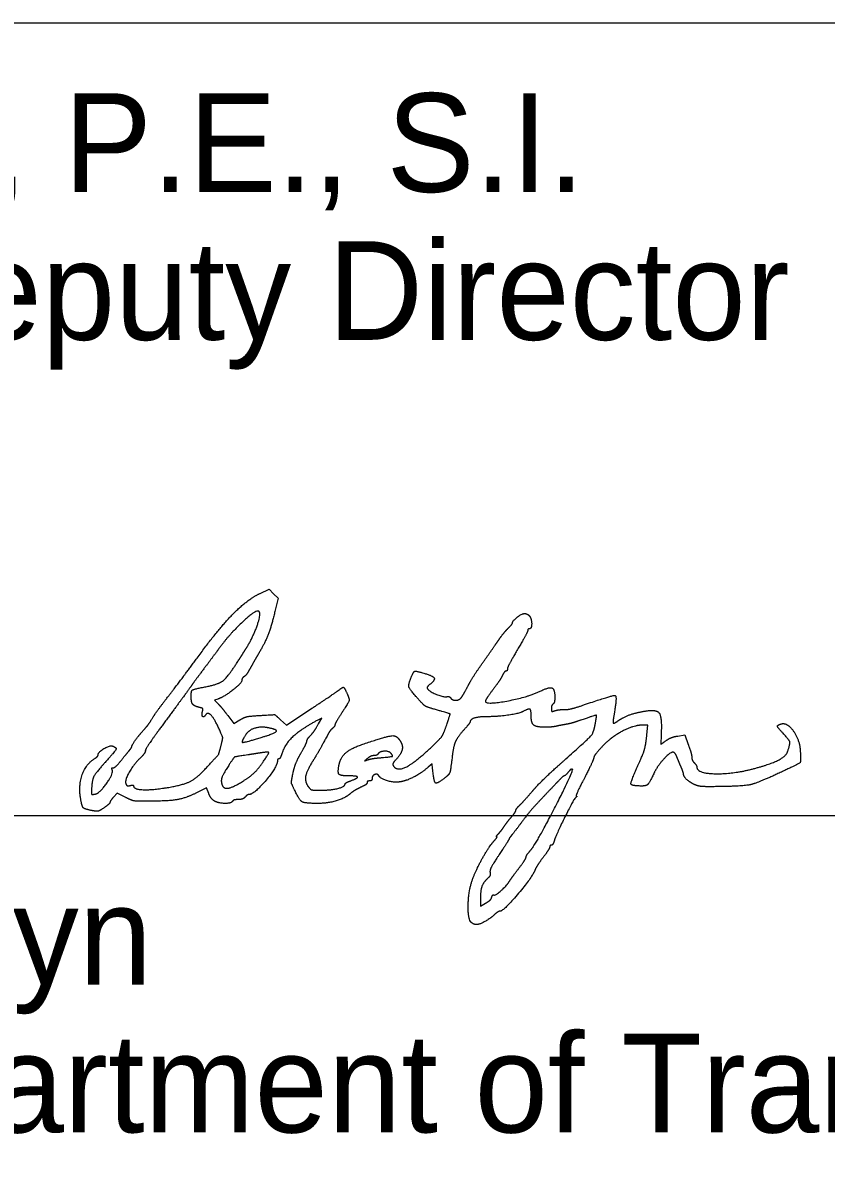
# Model space of a CAD drawing. Extents: x 0 to 34, y 0 to 22.
# Drawn here: x 25.648 to 26.788, y 7.199 to 8.816 of the extents above; entities that cross this region are included whole.
import ezdxf

# ---------------------------------------------------------------- set-up
doc = ezdxf.new("R2010")
doc.units = 0
doc.layers.add('SH_Data', color=7, linetype='Continuous')
doc.layers.add('SH_Text', color=7, linetype='Continuous')

msp = doc.modelspace()

# ---------------------------------------------------------------- linework, layer by layer
at = {"layer": 'SH_Data'}
for p, q in [((24.5, 8.816), (28, 8.816)), ((24.5, 7.691), (28, 7.691))]:
    msp.add_line(p, q, dxfattribs=at)
at = {"layer": 'SH_Text'}
for points in [[(25.9853, 8.0062), (25.9979, 8.012), (26.0042, 8.0057), (26.0106, 7.9993), (26.0062, 7.9806)], [(25.9253, 7.8562), (25.9203, 7.8546), (25.9255, 7.8495)], [(25.9392, 7.8328), (25.9477, 7.8213), (25.9565, 7.8265)], [(26.0143, 7.8265), (26.0224, 7.8189), (26.0587, 7.843)], [(26.0682, 7.8212), (26.0726, 7.8292), (26.0671, 7.8263)], [(26.534, 7.8053), (26.5355, 7.8191), (26.5277, 7.8191)], [(26.5779, 7.8037), (26.5876, 7.8053), (26.5926, 7.7917)], [(26.23, 7.7576), (26.2293, 7.7644), (26.2234, 7.7593)], [(25.7937, 7.7169), (25.7822, 7.7227), (25.7771, 7.7169)], [(25.9123, 7.722), (25.909, 7.73), (25.8951, 7.7231)], [(26.2977, 7.5714), (26.2977, 7.5621), (26.3052, 7.5664)]]:
    msp.add_lwpolyline(points, dxfattribs=at)
for points in [[(25.8957, 7.9143), (25.9254, 7.9549), (25.9672, 7.9978), (25.9853, 8.0062)], [(25.9838, 7.9804), (25.9802, 7.984), (25.9416, 7.9483), (25.9262, 7.927)], [(25.9655, 7.9283), (25.9749, 7.9432), (25.9869, 7.9773), (25.9838, 7.9804)], [(26.0062, 7.9806), (26.0012, 7.9595), (25.992, 7.9359), (25.9826, 7.9199)], [(26.3433, 7.9643), (26.3433, 7.9671), (26.3565, 7.9774), (26.3602, 7.9775)], [(26.3602, 7.9775), (26.3623, 7.9775), (26.3652, 7.9762), (26.3668, 7.9747)], [(26.3668, 7.9747), (26.3703, 7.9712), (26.3707, 7.9559), (26.3673, 7.9559)], [(26.3367, 7.9562), (26.3403, 7.9598), (26.3433, 7.9634), (26.3433, 7.9643)], [(26.3229, 7.9389), (26.3269, 7.9448), (26.3331, 7.9525), (26.3367, 7.9562)], [(26.3649, 7.9534), (26.3649, 7.952), (26.3584, 7.9399), (26.3505, 7.9266)], [(26.3673, 7.9559), (26.366, 7.9559), (26.3649, 7.9548), (26.3649, 7.9534)], [(25.9262, 7.927), (25.9226, 7.9221), (25.9132, 7.9094), (25.9053, 7.8989)], [(25.955, 7.9117), (25.9583, 7.9169), (25.963, 7.9244), (25.9655, 7.9283)], [(26.3013, 7.9079), (26.3092, 7.9192), (26.319, 7.9331), (26.3229, 7.9389)], [(26.3505, 7.9266), (26.3426, 7.9132), (26.3361, 7.9008), (26.3361, 7.8991)], [(25.8555, 7.8609), (25.8644, 7.8722), (25.8825, 7.8963), (25.8957, 7.9143)], [(25.9052, 7.873), (25.9258, 7.8768), (25.9398, 7.8877), (25.955, 7.9117)], [(25.9826, 7.9199), (25.9791, 7.914), (25.9739, 7.9048), (25.971, 7.8995)], [(25.9053, 7.8989), (25.8974, 7.8884), (25.8893, 7.8774), (25.8873, 7.8745)], [(25.971, 7.8995), (25.9682, 7.8943), (25.9644, 7.8891), (25.9626, 7.888)], [(26.1992, 7.8862), (26.203, 7.8952), (26.2061, 7.8963), (26.2188, 7.8925)], [(26.2188, 7.8925), (26.2308, 7.889), (26.2337, 7.8828), (26.226, 7.8769)], [(26.2799, 7.8743), (26.2837, 7.8816), (26.2933, 7.8967), (26.3013, 7.9079)], [(26.3341, 7.8959), (26.333, 7.8959), (26.3306, 7.893), (26.3288, 7.8893)], [(26.3361, 7.8991), (26.3361, 7.8973), (26.3352, 7.8959), (26.3341, 7.8959)], [(25.9593, 7.8826), (25.9593, 7.8788), (25.9335, 7.8588), (25.9253, 7.8562)], [(25.9626, 7.888), (25.9608, 7.887), (25.9593, 7.8845), (25.9593, 7.8826)], [(26.209, 7.8568), (26.1975, 7.8698), (26.1953, 7.8766), (26.1992, 7.8862)], [(26.226, 7.8769), (26.2233, 7.8749), (26.2218, 7.872), (26.2228, 7.8707)], [(26.3288, 7.8893), (26.3271, 7.8857), (26.3209, 7.8766), (26.3152, 7.8691)], [(25.834, 7.8315), (25.837, 7.8363), (25.8467, 7.8495), (25.8555, 7.8609)], [(25.8873, 7.8745), (25.8853, 7.8715), (25.87, 7.8506), (25.8532, 7.8279)], [(25.8873, 7.8609), (25.8873, 7.8677), (25.8914, 7.8705), (25.9052, 7.873)], [(25.8983, 7.8445), (25.8911, 7.8463), (25.8873, 7.852), (25.8873, 7.8609)], [(26.0587, 7.843), (26.0786, 7.8563), (26.0962, 7.8682), (26.0978, 7.8695)], [(26.0978, 7.8695), (26.1023, 7.8733), (26.1047, 7.8724), (26.1077, 7.8658)], [(26.1077, 7.8658), (26.1121, 7.8562), (26.1111, 7.8521), (26.1009, 7.8362)], [(26.2228, 7.8707), (26.2254, 7.8669), (26.2453, 7.8587), (26.25, 7.8595)], [(26.2706, 7.8581), (26.2719, 7.8598), (26.2761, 7.8671), (26.2799, 7.8743)], [(26.3152, 7.8691), (26.3096, 7.8617), (26.3049, 7.8544), (26.3049, 7.8531)], [(26.3049, 7.8531), (26.3049, 7.8478), (26.3645, 7.8587), (26.3825, 7.8673)], [(26.3825, 7.8673), (26.3955, 7.8735), (26.4033, 7.8703), (26.4033, 7.8589)], [(26.4456, 7.8482), (26.486, 7.8621), (26.4919, 7.8605), (26.4878, 7.8366)], [(25.9034, 7.8382), (25.9043, 7.8418), (25.9031, 7.8433), (25.8983, 7.8445)], [(25.9255, 7.8495), (25.9283, 7.8467), (25.9345, 7.8392), (25.9392, 7.8328)], [(26.2325, 7.8416), (26.2217, 7.8447), (26.2168, 7.8479), (26.209, 7.8568)], [(26.25, 7.8595), (26.2522, 7.8599), (26.2548, 7.859), (26.2556, 7.8577)], [(26.2556, 7.8577), (26.2578, 7.8542), (26.2678, 7.8545), (26.2706, 7.8581)], [(26.4009, 7.8491), (26.3996, 7.8483), (26.3985, 7.8455), (26.3985, 7.8428)], [(26.4033, 7.8589), (26.4033, 7.8544), (26.4022, 7.85), (26.4009, 7.8491)], [(26.4168, 7.8412), (26.421, 7.841), (26.4339, 7.8442), (26.4456, 7.8482)], [(25.8177, 7.8096), (25.8243, 7.8169), (25.8285, 7.8227), (25.834, 7.8315)], [(25.8532, 7.8279), (25.8364, 7.8053), (25.8226, 7.7851), (25.8225, 7.7831)], [(25.9077, 7.8335), (25.9052, 7.8296), (25.902, 7.8331), (25.9034, 7.8382)], [(25.9265, 7.8149), (25.9203, 7.8285), (25.9106, 7.8382), (25.9077, 7.8335)], [(25.9565, 7.8265), (25.963, 7.8304), (25.9706, 7.8321), (25.9857, 7.8329)], [(25.9857, 7.8329), (26.006, 7.8341), (26.0062, 7.8341), (26.0143, 7.8265)], [(26.1009, 7.8362), (26.0956, 7.8281), (26.0913, 7.8205), (26.0913, 7.8194)], [(26.2493, 7.8179), (26.255, 7.8347), (26.2546, 7.8353), (26.2325, 7.8416)], [(26.3075, 7.8311), (26.296, 7.8311), (26.2833, 7.8274), (26.2833, 7.824)], [(26.3583, 7.8385), (26.3527, 7.8355), (26.3225, 7.8311), (26.3075, 7.8311)], [(26.3697, 7.8338), (26.3697, 7.8411), (26.366, 7.8427), (26.3583, 7.8385)], [(26.389, 7.8162), (26.3766, 7.8162), (26.3697, 7.8225), (26.3697, 7.8338)], [(26.3985, 7.8428), (26.3985, 7.8389), (26.3995, 7.8383), (26.4039, 7.8397)], [(26.4039, 7.8397), (26.4069, 7.8407), (26.4127, 7.8413), (26.4168, 7.8412)], [(26.4609, 7.8216), (26.463, 7.8331), (26.4613, 7.8335), (26.4403, 7.8262)], [(26.4878, 7.8366), (26.4865, 7.829), (26.4857, 7.8224), (26.4862, 7.8219)], [(26.4938, 7.8257), (26.501, 7.8308), (26.5192, 7.8371), (26.5329, 7.8393)], [(26.5329, 7.8393), (26.5476, 7.8416), (26.5552, 7.8311), (26.5544, 7.8099)], [(25.9298, 7.7903), (25.9323, 7.8002), (25.932, 7.8024), (25.9265, 7.8149)], [(25.9975, 7.8152), (25.9866, 7.8174), (25.9693, 7.8123), (25.9649, 7.8057)], [(25.9869, 7.8017), (26.0061, 7.8076), (26.0101, 7.8127), (25.9975, 7.8152)], [(26.0671, 7.8263), (26.0437, 7.8137), (26.021, 7.793), (26.0168, 7.7806)], [(26.0554, 7.8031), (26.0608, 7.8091), (26.0633, 7.8127), (26.0682, 7.8212)], [(26.0877, 7.8144), (26.0858, 7.8128), (26.0827, 7.8086), (26.0809, 7.8051)], [(26.0913, 7.8194), (26.0913, 7.8182), (26.0897, 7.816), (26.0877, 7.8144)], [(26.231, 7.7906), (26.2414, 7.8006), (26.2455, 7.8068), (26.2493, 7.8179)], [(26.2739, 7.8119), (26.2655, 7.8024), (26.2597, 7.7899), (26.2581, 7.7771)], [(26.2833, 7.824), (26.2833, 7.8231), (26.2791, 7.8177), (26.2739, 7.8119)], [(26.4057, 7.8176), (26.4024, 7.8168), (26.3949, 7.8162), (26.389, 7.8162)], [(26.4189, 7.8202), (26.4149, 7.8195), (26.409, 7.8184), (26.4057, 7.8176)], [(26.4161, 7.7686), (26.4516, 7.8002), (26.4585, 7.8083), (26.4609, 7.8216)], [(26.4403, 7.8262), (26.4325, 7.8235), (26.4229, 7.8208), (26.4189, 7.8202)], [(26.5277, 7.8191), (26.515, 7.8191), (26.4812, 7.8007), (26.4691, 7.7872)], [(26.4862, 7.8219), (26.4867, 7.8214), (26.4901, 7.8231), (26.4938, 7.8257)], [(26.7245, 7.8105), (26.7192, 7.8162), (26.719, 7.8189), (26.7236, 7.8206)], [(26.7236, 7.8206), (26.7322, 7.8239), (26.7506, 7.799), (26.7516, 7.7827)], [(25.8033, 7.7891), (25.8033, 7.7908), (25.8124, 7.8038), (25.8177, 7.8096)], [(25.9649, 7.8057), (25.9579, 7.795), (25.9625, 7.7942), (25.9869, 7.8017)], [(26.0429, 7.779), (26.0473, 7.7867), (26.0512, 7.7943), (26.0514, 7.7961)], [(26.0514, 7.7961), (26.0517, 7.7978), (26.0535, 7.801), (26.0554, 7.8031)], [(26.0809, 7.8051), (26.0727, 7.7897), (26.0649, 7.7759), (26.0588, 7.7662)], [(26.1347, 7.7934), (26.1665, 7.804), (26.1799, 7.8044), (26.185, 7.7949)], [(26.5194, 7.7575), (26.5284, 7.7774), (26.5324, 7.7906), (26.534, 7.8053)], [(26.5544, 7.8099), (26.5537, 7.7915), (26.5536, 7.7918), (26.5613, 7.7973)], [(26.5613, 7.7973), (26.5651, 7.8), (26.5726, 7.8029), (26.5779, 7.8037)], [(26.7336, 7.7814), (26.7376, 7.7932), (26.736, 7.7981), (26.7245, 7.8105)], [(25.7553, 7.7771), (25.7554, 7.7809), (25.7721, 7.7908), (25.7759, 7.7894)], [(25.7759, 7.7894), (25.7819, 7.7871), (25.7796, 7.7822), (25.7653, 7.7663)], [(25.7888, 7.7699), (25.7941, 7.7765), (25.7996, 7.7832), (25.8009, 7.7848)], [(25.8009, 7.7848), (25.8022, 7.7864), (25.8033, 7.7884), (25.8033, 7.7891)], [(25.8225, 7.7831), (25.8224, 7.7812), (25.8191, 7.7763), (25.8151, 7.7724)], [(25.9101, 7.7598), (25.9262, 7.7774), (25.9265, 7.7779), (25.9298, 7.7903)], [(25.9851, 7.7796), (25.9795, 7.7787), (25.9717, 7.7775), (25.9677, 7.7769)], [(25.9901, 7.7679), (25.9979, 7.7793), (25.997, 7.7814), (25.9851, 7.7796)], [(26.0168, 7.7806), (26.0151, 7.7754), (26.0128, 7.7711), (26.0117, 7.7711)], [(26.032, 7.7512), (26.0336, 7.7589), (26.0385, 7.7714), (26.0429, 7.779)], [(26.0971, 7.7623), (26.0992, 7.7736), (26.1154, 7.787), (26.1347, 7.7934)], [(26.1708, 7.7792), (26.168, 7.7825), (26.1546, 7.7817), (26.1523, 7.7781)], [(26.1549, 7.7728), (26.1716, 7.7743), (26.174, 7.7753), (26.1708, 7.7792)], [(26.174, 7.7617), (26.1793, 7.7531), (26.2061, 7.7666), (26.231, 7.7906)], [(26.185, 7.7949), (26.1882, 7.7889), (26.1848, 7.7775), (26.1774, 7.7696)], [(26.4691, 7.7872), (26.4632, 7.7807), (26.4585, 7.7741), (26.4585, 7.7726)], [(26.5709, 7.7807), (26.5666, 7.7807), (26.5483, 7.7602), (26.5436, 7.7501)], [(26.5765, 7.7741), (26.575, 7.7778), (26.5725, 7.7807), (26.5709, 7.7807)], [(26.5926, 7.7917), (26.5954, 7.7843), (26.5977, 7.7761), (26.5977, 7.7736)], [(26.6847, 7.7571), (26.7084, 7.7634), (26.7314, 7.7748), (26.7336, 7.7814)], [(26.7516, 7.7827), (26.7526, 7.7674), (26.7499, 7.7643), (26.7265, 7.7533)], [(25.7304, 7.7155), (25.7275, 7.734), (25.7382, 7.764), (25.7506, 7.7718)], [(25.7653, 7.7663), (25.7516, 7.7511), (25.7466, 7.741), (25.746, 7.7272)], [(25.7506, 7.7718), (25.7532, 7.7734), (25.7553, 7.7758), (25.7553, 7.7771)], [(25.7765, 7.7586), (25.7779, 7.7583), (25.7834, 7.7633), (25.7888, 7.7699)], [(25.8151, 7.7724), (25.8053, 7.7628), (25.7929, 7.7407), (25.7947, 7.736)], [(25.9677, 7.7769), (25.9499, 7.7743), (25.9479, 7.7732), (25.9406, 7.762)], [(25.9602, 7.7392), (25.9714, 7.7462), (25.9824, 7.7567), (25.9901, 7.7679)], [(26.0097, 7.7681), (26.0095, 7.7596), (25.9764, 7.7207), (25.9693, 7.7207)], [(26.0117, 7.7711), (26.0106, 7.7711), (26.0097, 7.7698), (26.0097, 7.7681)], [(26.0588, 7.7662), (26.0508, 7.7536), (26.0486, 7.7384), (26.0537, 7.7316)], [(26.138, 7.7721), (26.1334, 7.7684), (26.1334, 7.7684), (26.1381, 7.77)], [(26.1468, 7.7759), (26.1445, 7.7759), (26.1405, 7.7742), (26.138, 7.7721)], [(26.1381, 7.77), (26.1407, 7.771), (26.1483, 7.7722), (26.1549, 7.7728)], [(26.1523, 7.7781), (26.1516, 7.7769), (26.1491, 7.7759), (26.1468, 7.7759)], [(26.1774, 7.7696), (26.1746, 7.7667), (26.1731, 7.7631), (26.174, 7.7617)], [(26.2581, 7.7771), (26.2553, 7.7546), (26.2536, 7.7492), (26.2479, 7.7447)], [(26.372, 7.7259), (26.3792, 7.7343), (26.399, 7.7535), (26.4161, 7.7686)], [(26.4585, 7.7726), (26.4585, 7.771), (26.4525, 7.7581), (26.4453, 7.744)], [(26.5824, 7.76), (26.5806, 7.7641), (26.578, 7.7705), (26.5765, 7.7741)], [(26.5977, 7.7736), (26.5977, 7.7711), (26.5993, 7.7675), (26.6013, 7.7655)], [(26.6013, 7.7655), (26.6033, 7.7635), (26.6049, 7.7608), (26.6049, 7.7595)], [(25.7509, 7.7212), (25.7572, 7.7221), (25.7773, 7.7505), (25.7753, 7.7557)], [(25.7753, 7.7557), (25.7745, 7.7577), (25.7751, 7.759), (25.7765, 7.7586)], [(25.8536, 7.7305), (25.8763, 7.7342), (25.8959, 7.7444), (25.9101, 7.7598)], [(25.9406, 7.762), (25.9324, 7.7493), (25.9292, 7.7395), (25.9315, 7.7337)], [(26.034, 7.7272), (26.0296, 7.7363), (26.0294, 7.7385), (26.032, 7.7512)], [(26.1106, 7.7471), (26.0991, 7.7471), (26.0951, 7.7517), (26.0971, 7.7623)], [(26.114, 7.7402), (26.1243, 7.7439), (26.1227, 7.7471), (26.1106, 7.7471)], [(26.1536, 7.7473), (26.1516, 7.7506), (26.1441, 7.7474), (26.1441, 7.7433)], [(26.1849, 7.7388), (26.1763, 7.7372), (26.1565, 7.7426), (26.1536, 7.7473)], [(26.2234, 7.7593), (26.214, 7.7511), (26.194, 7.7405), (26.1849, 7.7388)], [(26.2479, 7.7447), (26.2362, 7.7355), (26.2318, 7.7386), (26.23, 7.7576)], [(26.3694, 7.6421), (26.3771, 7.6508), (26.4303, 7.7545), (26.4282, 7.7566)], [(26.4167, 7.7471), (26.416, 7.7471), (26.412, 7.7436), (26.4079, 7.7393)], [(26.4225, 7.7525), (26.4201, 7.7496), (26.4175, 7.7471), (26.4167, 7.7471)], [(26.4282, 7.7566), (26.4275, 7.7573), (26.4249, 7.7555), (26.4225, 7.7525)], [(26.5267, 7.7327), (26.5122, 7.7327), (26.5106, 7.7382), (26.5194, 7.7575)], [(26.5436, 7.7501), (26.5379, 7.7377), (26.5331, 7.7327), (26.5267, 7.7327)], [(26.5858, 7.7504), (26.5857, 7.7515), (26.5842, 7.7558), (26.5824, 7.76)], [(26.6014, 7.7348), (26.5944, 7.7381), (26.5859, 7.7465), (26.5858, 7.7504)], [(26.6049, 7.7595), (26.6049, 7.7509), (26.6555, 7.7495), (26.6847, 7.7571)], [(26.7265, 7.7533), (26.6917, 7.737), (26.6707, 7.7322), (26.6313, 7.7318)], [(25.7947, 7.736), (25.7956, 7.7336), (25.7979, 7.7327), (25.8009, 7.7334)], [(25.8009, 7.7334), (25.8035, 7.7341), (25.8057, 7.7338), (25.8057, 7.7327)], [(25.8057, 7.7327), (25.8057, 7.7281), (25.8313, 7.7269), (25.8536, 7.7305)], [(25.9315, 7.7337), (25.9335, 7.7284), (25.9471, 7.731), (25.9602, 7.7392)], [(26.0537, 7.7316), (26.0566, 7.7277), (26.0601, 7.7268), (26.0713, 7.7268)], [(26.0713, 7.7268), (26.0853, 7.7267), (26.1057, 7.7318), (26.1057, 7.7354)], [(26.1057, 7.7354), (26.1057, 7.7364), (26.1094, 7.7386), (26.114, 7.7402)], [(26.1315, 7.7326), (26.1242, 7.7293), (26.1165, 7.7247), (26.1123, 7.7212)], [(26.1369, 7.7375), (26.1369, 7.7361), (26.1345, 7.7339), (26.1315, 7.7326)], [(26.1405, 7.7399), (26.1385, 7.7399), (26.1369, 7.7388), (26.1369, 7.7375)], [(26.1441, 7.7433), (26.1441, 7.7414), (26.1425, 7.7399), (26.1405, 7.7399)], [(26.4079, 7.7393), (26.4038, 7.735), (26.3933, 7.724), (26.3845, 7.7147)], [(26.4453, 7.744), (26.438, 7.7299), (26.4329, 7.7183), (26.4339, 7.7183)], [(26.6313, 7.7318), (26.6164, 7.7316), (26.6061, 7.7326), (26.6014, 7.7348)], [(25.747, 7.6978), (25.7361, 7.6998), (25.7323, 7.7039), (25.7304, 7.7155)], [(25.746, 7.7272), (25.7458, 7.7216), (25.7466, 7.7205), (25.7509, 7.7212)], [(25.7771, 7.7169), (25.7744, 7.7137), (25.7721, 7.7103), (25.7721, 7.7093)], [(25.8245, 7.7111), (25.8089, 7.7111), (25.803, 7.7122), (25.7937, 7.7169)], [(25.8951, 7.7231), (25.8796, 7.7154), (25.8544, 7.7111), (25.8245, 7.7111)], [(25.9205, 7.7113), (25.9179, 7.7128), (25.9142, 7.7175), (25.9123, 7.722)], [(25.9641, 7.7171), (25.9625, 7.7152), (25.9581, 7.7135), (25.9543, 7.7135)], [(25.9693, 7.7207), (25.9681, 7.7207), (25.9657, 7.7191), (25.9641, 7.7171)], [(26.0658, 7.708), (26.0483, 7.7081), (26.0413, 7.7123), (26.034, 7.7272)], [(26.1123, 7.7212), (26.1046, 7.7149), (26.0803, 7.7079), (26.0658, 7.708)], [(26.3535, 7.7055), (26.3565, 7.7083), (26.3648, 7.7175), (26.372, 7.7259)], [(26.3845, 7.7147), (26.3757, 7.7054), (26.3658, 7.6942), (26.3625, 7.6897)], [(26.4331, 7.7165), (26.4304, 7.7147), (26.4052, 7.6637), (26.4022, 7.6541)], [(26.4339, 7.7183), (26.4349, 7.7183), (26.4345, 7.7175), (26.4331, 7.7165)], [(25.7637, 7.7019), (25.7572, 7.6974), (25.7536, 7.6965), (25.747, 7.6978)], [(25.7721, 7.7093), (25.7721, 7.7083), (25.7683, 7.705), (25.7637, 7.7019)], [(25.9461, 7.7111), (25.9441, 7.7079), (25.9266, 7.7081), (25.9205, 7.7113)], [(25.9543, 7.7135), (25.9506, 7.7135), (25.9469, 7.7125), (25.9461, 7.7111)], [(26.3415, 7.6884), (26.3451, 7.6927), (26.3481, 7.6971), (26.3481, 7.6983)], [(26.3481, 7.6983), (26.3482, 7.6994), (26.3506, 7.7027), (26.3535, 7.7055)], [(26.3313, 7.6751), (26.3333, 7.6782), (26.3379, 7.6842), (26.3415, 7.6884)], [(26.3625, 7.6897), (26.3544, 7.6788), (26.3439, 7.665), (26.3409, 7.6614)], [(26.3235, 7.6651), (26.3258, 7.6676), (26.3293, 7.6721), (26.3313, 7.6751)], [(26.2875, 7.6027), (26.2934, 7.6176), (26.3105, 7.6475), (26.3176, 7.6553)], [(26.3176, 7.6553), (26.3203, 7.6583), (26.3218, 7.6607), (26.3209, 7.6607)], [(26.3209, 7.6607), (26.32, 7.6607), (26.3212, 7.6627), (26.3235, 7.6651)], [(26.3385, 7.6576), (26.3385, 7.657), (26.3322, 7.6471), (26.3244, 7.6354)], [(26.3409, 7.6614), (26.3396, 7.6598), (26.3385, 7.6581), (26.3385, 7.6576)], [(26.4022, 7.6541), (26.4013, 7.6512), (26.3996, 7.6487), (26.3983, 7.6487)], [(26.3244, 7.6354), (26.3158, 7.6224), (26.3108, 7.6126), (26.3115, 7.6099)], [(26.3625, 7.6318), (26.3625, 7.6331), (26.3656, 7.6377), (26.3694, 7.6421)], [(26.3961, 7.6462), (26.3961, 7.6449), (26.3918, 7.6381), (26.3866, 7.6312)], [(26.3983, 7.6487), (26.3971, 7.6487), (26.3961, 7.6476), (26.3961, 7.6462)], [(26.3523, 7.6159), (26.3579, 7.6233), (26.3625, 7.6304), (26.3625, 7.6318)], [(26.3866, 7.6312), (26.3814, 7.6243), (26.3763, 7.6163), (26.3752, 7.6135)], [(26.2857, 7.5383), (26.2798, 7.5421), (26.281, 7.5864), (26.2875, 7.6027)], [(26.3078, 7.6013), (26.3019, 7.5961), (26.2977, 7.5838), (26.2977, 7.5714)], [(26.3115, 7.6099), (26.3122, 7.6074), (26.3106, 7.6038), (26.3078, 7.6013)], [(26.3752, 7.6135), (26.3716, 7.6036), (26.3304, 7.5551), (26.3257, 7.5551)], [(26.3397, 7.5987), (26.341, 7.6008), (26.3467, 7.6086), (26.3523, 7.6159)], [(26.3169, 7.5779), (26.3188, 7.5768), (26.3355, 7.5919), (26.3397, 7.5987)], [(26.3052, 7.5664), (26.3094, 7.5688), (26.3133, 7.5726), (26.3139, 7.5749)], [(26.3139, 7.5749), (26.3145, 7.5772), (26.3159, 7.5786), (26.3169, 7.5779)], [(26.3257, 7.5551), (26.3243, 7.5551), (26.321, 7.5531), (26.3183, 7.5506)], [(26.2922, 7.536), (26.2906, 7.536), (26.2877, 7.537), (26.2857, 7.5383)], [(26.3183, 7.5506), (26.3121, 7.5449), (26.2961, 7.5359), (26.2922, 7.536)]]:
    msp.add_open_spline(points, degree=2, dxfattribs=at)

# ---------------------------------------------------------------- texts
for s, p in [('Pat McColley, P.E., S.I.', (24.5, 8.576)), ('District       Deputy Director', (24.5, 8.366)), ('Pamela Boratyn', (24.5, 7.451)), ('Director, Department of Transportation', (24.5, 7.241))]:
    msp.add_text(s, height=0.14, dxfattribs=at).set_placement(p)

doc.saveas('drawing.dxf')
